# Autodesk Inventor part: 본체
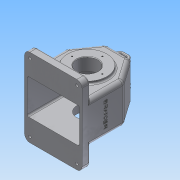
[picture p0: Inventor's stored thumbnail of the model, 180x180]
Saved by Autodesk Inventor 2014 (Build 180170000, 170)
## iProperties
Created: 2016-12
Part Number: 본체
Material: Aluminum 6061
Document SubType Name: Modeling
Designer: user
Mass: 1067.29 g
Surface Area: 1138.05 cm^2
Volume: 393.834 cm^3
Density: 2.71 g/cm^3
Appearance: Aluminum - Flat
Author: user
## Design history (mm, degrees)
sketch "Sketch1"
  geometry: L1 (-55, 0)-(-23.491, 45); L2 (-23.491, 45)-(0, 45); L3 (0, 45)-(0, -80); L4 (0, -80)-(-55, -80); L5 (-55, -80)-(-55, 0); L6 (-77, 0)-(77, 0) reference; L7 (55, 0)-(23.491, 45); L8 (0, -80)-(55, -80); L9 (55, -80)-(55, 0); L10 (23.491, 45)-(0, 45); 1 further point
  constraints: 18 end point, 3 symmetric about line, 2 horizontal, 2 point on line, 1 parallel, 1 perpendicular
  dimensions: "d0" = 55 deg angle of L6 L1; "d1" = 80 distance between parallel lines of L6 L4; "d2" = 125 distance between parallel lines of L2 L4; "d3" = 55 distance between parallel lines of L3 L5
extrude "Extrusion1" new body sketch "Sketch1" stored distance "d4" = 77; taper "d5" = 0 deg
shell "Shell1" dims "d32" = 5
sketch "Sketch2"
  geometry: L1 (0, -113.5)-(110, -113.5); L2 (110, -113.5)-(110, 36.5); L3 (110, 36.5)-(0, 36.5); L4 (0, 36.5)-(0, -113.5); L5 (0, -113.5)-(110, 36.5); L6 (110, -113.5)-(0, 36.5); 1 further point
  constraints: 12 end point, 2 midpoint, 2 parallel, 1 horizontal, 1 perpendicular
  dimensions: "d6" = 110 distance between parallel lines of L2 L4; "d7" = 150 distance of L1.end L2.end
extrude "Extrusion2" join sketch "Sketch2" distance "d8" = 15; taper "d9" = 0 deg
workplane "Work Plane1"
sketch "Sketch3"
  geometry: L1 (23.491, 45)-(-23.491, 45) reference; L2 (-12.5, 45)-(12.5, 45); L3 (12.5, 45)-(12.5, 60); L4 (12.5, 60)-(-12.5, 60); L5 (-12.5, 60)-(-12.5, 45); L6 (55, -80)-(-55, -80) reference; L7 (-7.5, 45)-(7.5, 45); L8 (7.5, 45)-(7.5, 55); L9 (7.5, 55)-(-7.5, 55); L10 (-7.5, 55)-(-7.5, 45); 3 further points
  constraints: 16 end point, 4 parallel, 2 horizontal, 2 midpoint, 2 perpendicular, 2 point on line, 2 vertical alignment
  dimensions: "d11" = 25 distance of L3.end L4.end; "d12" = 140 distance between parallel lines of L6 L4; "d13" = 15 distance of L8.end L9.end; "d14" = 5 distance between parallel lines of L9 L4
extrude "Extrusion3" join sketch "Sketch3" distance "d15" = 8; taper "d16" = 0 deg
mirror "Mirror1"
fillet "Fillet1" dims "d17" = 8
fillet "Fillet2" dims "d18" = 3
fillet "Fillet3" dims "d19" = 3
fillet "Fillet4" dims "d20" = 1
fillet "Fillet6" dims "d22" = 1
fillet "Fillet7" dims "d23" = 1
fillet "Fillet8" dims "d24" = 1
sketch "Sketch4"
  geometry: L1 (55, -80)-(-55, -80) reference; C1 r 31 at (0, -15); 1 further point
  constraints: 1 centre point
  dimensions: "d25" = 62 diameter of C1; "d26" = 65 distance from line of L1 C1.centre
extrude "Extrusion4" join sketch "Sketch4" distance "d27" = 10; taper "d28" = 0 deg
sketch "Sketch5"
  geometry: C1 r 31 at (0, -15) reference; C2 r 37.5 at (0, -15); 1 further point
  constraints: 1 centre point, 1 coincident
  dimensions: "d29" = 75 diameter of C2
extrude "Extrusion5" join sketch "Sketch5" distance "d30" = 5; taper "d31" = 0 deg
sketch "Sketch6"
  geometry: L1 (5, -108.5)-(105, -108.5); L2 (105, -108.5)-(105, -41.5); L3 (105, -41.5)-(5, -41.5); L4 (5, -41.5)-(5, -108.5); L5 (5, -108.5)-(105, -41.5); L6 (105, -108.5)-(5, -41.5); 1 further point
  constraints: 12 end point, 2 midpoint, 2 parallel, 1 horizontal, 1 perpendicular
extrude "Extrusion6" cut sketch "Sketch6" distance "d33" = 15; taper "d34" = 0 deg
fillet "Fillet9" dims "d35" = 10
fillet "Fillet10" dims "d36" = 10
fillet "Fillet11" dims "d37" = 8
fillet "Fillet12" dims "d38" = 3
fillet "Fillet13" dims "d39" = 3
fillet "Fillet14" dims "d40" = 3
fillet "Fillet15" dims "d41" = 5
sketch "Sketch7"
  geometry: L1 (36.147, 33.5)-(-2.522, 33.5) reference; L2 (26, 33.5)-(12, 19.5); L3 (22.5, 43.5)-(-52.5, 43.5) reference; L4 (-15, 33.5)-(-15, 19.5); L5 (12, 19.5)-(-15, 19.5); L6 (26, 33.5)-(-15, 33.5); L7 (-2.522, 33.5)-(-80, 33.5) reference; 1 further point
  constraints: 8 end point, 2 perpendicular, 2 point on line
  dimensions: "d42" = 24 distance between parallel lines of L3 L5; "d43" = 135 deg angle of L5 L2; "d44" = 54 diameter of L2.end L4
revolve "Revolution1" sketch "Sketch7" stored, may be unused: angle "d45" = 90 deg
fillet "Fillet16" dims "d46" = 3
fillet "Fillet17" dims "d47" = 3
sketch "Sketch8"
  geometry: C1 r 37.5 at (0, 0) reference; C2 r 20 at (0, 0); 1 further point
  constraints: 1 centre point, 1 coincident
  dimensions: "d48" = 40 diameter of C2
extrude "Extrusion7" cut sketch "Sketch8" stored distance "d49" = 15; taper "d50" = 0 deg
chamfer "Chamfer1" distance "d51" = 1; stored, may be unused: second distance "d52" = 2, angle "d53" = 45 deg
sketch "Sketch9" dims "d54" = 58
  geometry: C1 r 21 at (0, 0) reference; 3 further points
  constraints: 1 coincident, 1 vertical alignment, 2 other
hole "Hole1" sketch "Sketch9" at (0, 29) diameter "d55" = 2.459; stored, may be unused: countersink angle "d59" = 90 deg, drill point angle "d61" = 118 deg; dims "d56" = 6, "d57" = 4, "d58" = 2, "d60" = 8
pattern_circular "Circular Pattern1" dims angle "d63" = 360 deg
sketch "Sketch10" dims "d65" = 52
  geometry: C1 r 21 at (0, 0) reference; 3 further points
  constraints: 1 coincident, 1 vertical alignment, 2 other
hole "Hole2" sketch "Sketch10" at (0, 26) diameter "d66" = 2.459; stored, may be unused: countersink angle "d70" = 90 deg, drill point angle "d72" = 118 deg; dims "d67" = 6, "d68" = 4, "d69" = 2, "d71" = 8
pattern_circular "Circular Pattern2" dims angle "d74" = 360 deg
sketch "Sketch11"
  geometry: L1 (102, 72)-(8, 72) reference; L2 (5, 69)-(5, 8) reference; L3 (8, 5)-(102, 5) reference; L4 (105, 8)-(105, 69) reference; L5 (102, -3)-(8, -3) reference; L6 (0, 8)-(0, 69) reference; L7 (8, 80)-(102, 80) reference; L8 (110, 69)-(110, 8) reference; L9 (107, -26.5)-(107, -1.798) reference; L10 (10, -33.5)-(100, -33.5) reference; L11 (3, -1.798)-(3, -26.5) reference; L12 (3, 103.5)-(3, 78.798) reference; L13 (100, 110.5)-(10, 110.5) reference; L14 (107, 78.798)-(107, 103.5) reference; A1 r 7 centre (100, 103.5) between (107, 103.5) and (100, 110.5) reference; A2 r 7 centre (10, 103.5) between (10, 110.5) and (3, 103.5) reference; A3 r 3 centre (102, 69) between (105, 69) and (102, 72) reference; A4 r 3 centre (8, 69) between (8, 72) and (5, 69) reference; A5 r 3 centre (8, 8) between (5, 8) and (8, 5) reference; A6 r 3 centre (102, 8) between (102, 5) and (105, 8) reference; A7 r 11 centre (102, 8) between (102, -3) and (107, -1.798) reference; A8 r 11 centre (8, 8) between (3, -1.798) and (8, -3) reference; A9 r 8 centre (8, 8) between (0, 8) and (0.585, 4.998) reference; A10 r 8 centre (8, 69) between (0.585, 72.002) and (0, 69) reference; A11 r 11 centre (8, 69) between (8, 80) and (3, 78.798) reference; A12 r 11 centre (102, 69) between (107, 78.798) and (102, 80) reference; A13 r 8 centre (102, 69) between (110, 69) and (109.415, 72.002) reference; A14 r 8 centre (102, 8) between (109.415, 4.998) and (110, 8) reference; A15 r 7 centre (100, -26.5) between (100, -33.5) and (107, -26.5) reference; A16 r 7 centre (10, -26.5) between (3, -26.5) and (10, -33.5) reference; A17 r 7 centre (10, 103.5) between (10, 110.5) and (3, 103.5) reference; A18 r 7 centre (100, 103.5) between (107, 103.5) and (100, 110.5) reference; 1 further point
  constraints: 4 other
hole "Hole3" sketch "Sketch11" at (10, 103.5), (100, 103.5), (100, -26.5), (10, -26.5) diameter "d76" = 5; stored, may be unused: countersink angle "d80" = 90 deg, drill point angle "d82" = 118 deg; dims "d77" = 6, "d78" = 12, "d79" = 5, "d81" = 8
sketch "Sketch12"
  geometry: L1 (0, 0)-(130, 0) reference; L2 (26.5, 76.847)-(26.5, 18) reference; 2 further points
  constraints: 1 other
  dimensions: "d83" = 38.5 distance from line of point (65, 45) L2; "d84" = 45 distance from line of L1 point (65, 45)
emboss "Emboss1" sketch "Sketch12" dims "d0" = 55 deg, "d1" = 80, "d2" = 125, "d3" = 55, "d85" = 0.5, "d86" = 0
body "Solid1"
node "Project Cut Edges1"
other parameters: "d10" = 18
